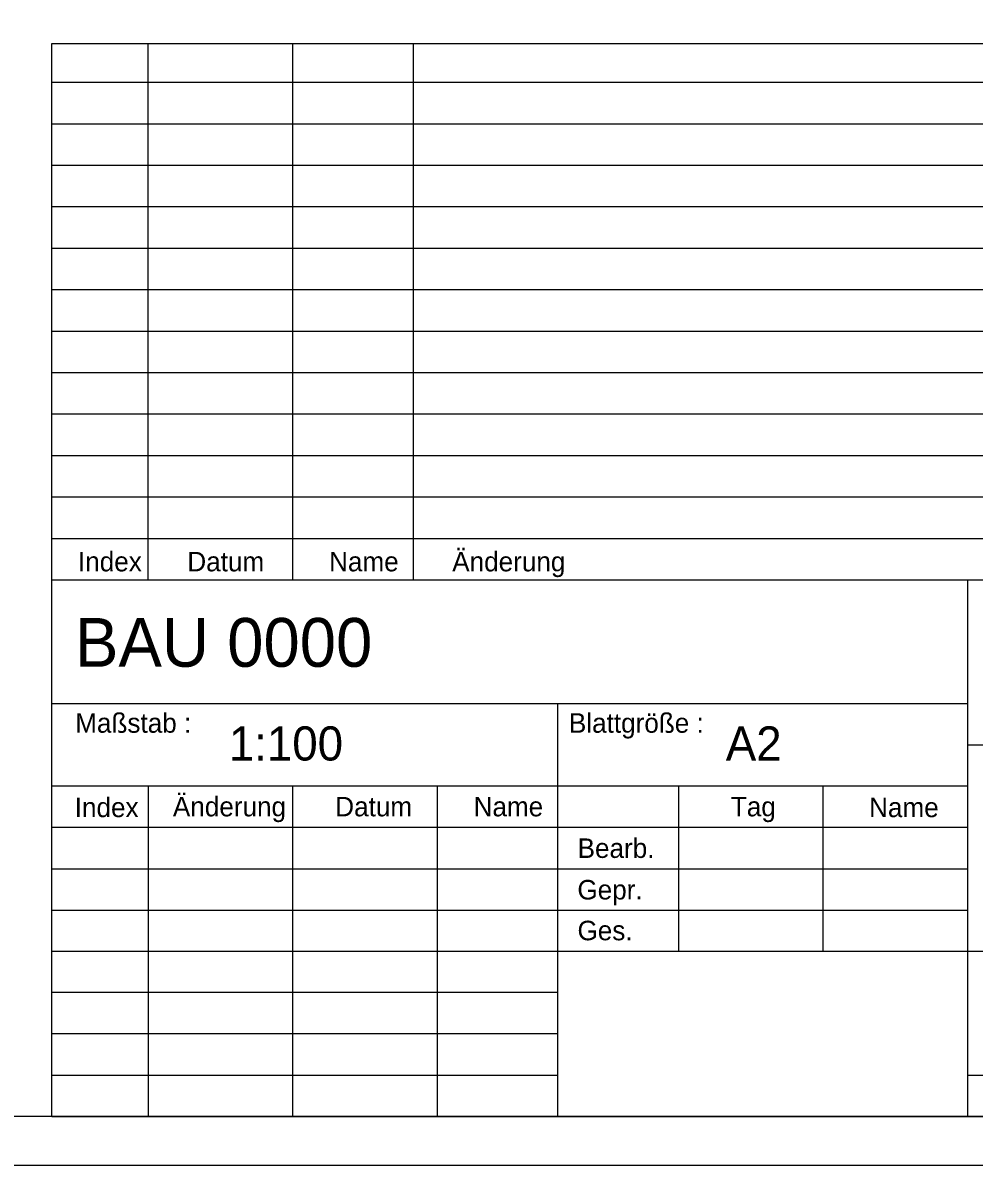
# Model space of a CAD drawing. Extents: x 0 to 59.4, y 0 to 42.
# Drawn here: x 40.82 to 50.57, y 0 to 11.71 of the extents above; entities that cross this region are included whole.
import ezdxf

# ---------------------------------------------------------------- set-up
doc = ezdxf.new("R2010")
doc.units = 0
doc.layers.add('90_Plankopf', color=7, linetype='Continuous')

msp = doc.modelspace()

# ---------------------------------------------------------------- linework, layer by layer
at = {"layer": '90_Plankopf'}
for p, q in [((41.112, 5.999), (41.112, 11.498)), ((41.112, 11.498), (58.9, 11.498)), ((42.1, 5.999), (42.1, 11.498)), ((43.583, 5.999), (43.583, 11.498)), ((44.818, 5.999), (44.818, 11.498)), ((41.112, 11.099), (58.9, 11.099)), ((41.112, 10.674), (58.9, 10.674)), ((41.112, 10.249), (58.9, 10.249)), ((41.112, 9.824), (58.9, 9.824)), ((41.112, 9.399), (58.9, 9.399)), ((41.112, 8.974), (58.9, 8.974)), ((41.112, 8.549), (58.9, 8.549)), ((41.112, 8.124), (58.9, 8.124)), ((41.112, 7.699), (58.9, 7.699)), ((41.112, 7.274), (58.9, 7.274)), ((41.112, 6.849), (58.9, 6.849)), ((41.112, 6.424), (58.9, 6.424)), ((41.112, 5.999), (58.9, 5.999)), ((41.112, 0.5), (41.112, 5.999)), ((41.112, 5.999), (58.9, 5.999)), ((50.5, 0.5), (50.5, 5.999)), ((41.112, 4.73), (50.5, 4.73)), ((46.3, 0.5), (46.3, 4.73)), ((50.5, 4.307), (58.9, 4.307)), ((41.112, 3.887), (50.5, 3.887)), ((42.1, 3.884), (42.1, 0.5)), ((43.583, 0.5), (43.583, 3.884)), ((45.065, 0.5), (45.065, 3.884)), ((47.535, 3.884), (47.535, 2.192)), ((49.018, 2.192), (49.018, 3.884)), ((41.112, 3.463), (50.5, 3.463)), ((41.112, 3.038), (50.5, 3.038)), ((41.112, 2.615), (50.5, 2.615)), ((41.112, 2.192), (50.5, 2.192)), ((41.112, 2.192), (50.5, 2.192)), ((46.3, 2.192), (50.5, 2.192)), ((50.5, 2.192), (58.9, 2.192)), ((46.3, 1.769), (41.112, 1.769)), ((46.3, 1.346), (41.112, 1.346)), ((41.112, 0.923), (46.3, 0.923)), ((50.5, 0.923), (58.9, 0.923)), ((58.9, 0.5), (41.112, 0.5)), ((41.112, 0.5), (46.3, 0.5)), ((42.28, 0.5), (58.9, 0.5)), ((42.28, 0.5), (58.9, 0.5))]:
    msp.add_line(p, q, dxfattribs=at)
for points in [[(0, 0), (59.4, 0), (59.4, 42), (0, 42)], [(2.5, 41.5), (58.9, 41.5), (58.9, 0.5), (2.5, 0.5)]]:
    msp.add_lwpolyline(points, close=True, dxfattribs=at)

# ---------------------------------------------------------------- texts
for s, height, p in [('Änderung', 0.2, (45.216, 6.086)), ('Index', 0.2, (41.38, 6.086)), ('Datum', 0.2, (42.501, 6.086)), ('Name', 0.2, (43.954, 6.086)), ('BAU 0000      ', 0.5, (41.349, 5.108)), ('Maßstab :', 0.2, (41.352, 4.432)), ('Blattgröße :', 0.19999, (46.412, 4.432)), ('1:100    ', 0.35, (42.926, 4.147)), ('A2       ', 0.35, (48.02, 4.147)), ('Index', 0.2, (41.347, 3.567)), ('Änderung', 0.2, (42.353, 3.575)), ('Datum', 0.2, (44.017, 3.575)), ('Name', 0.2, (45.435, 3.575)), ('Tag', 0.2, (48.072, 3.575)), ('Name', 0.2, (49.489, 3.567)), ('Bearb.', 0.2, (46.501, 3.149)), ('Gepr.', 0.2, (46.499, 2.723)), ('Ges.', 0.2, (46.5, 2.305))]:
    msp.add_text(s, height=height, dxfattribs=at).set_placement(p)

doc.saveas('drawing.dxf')
